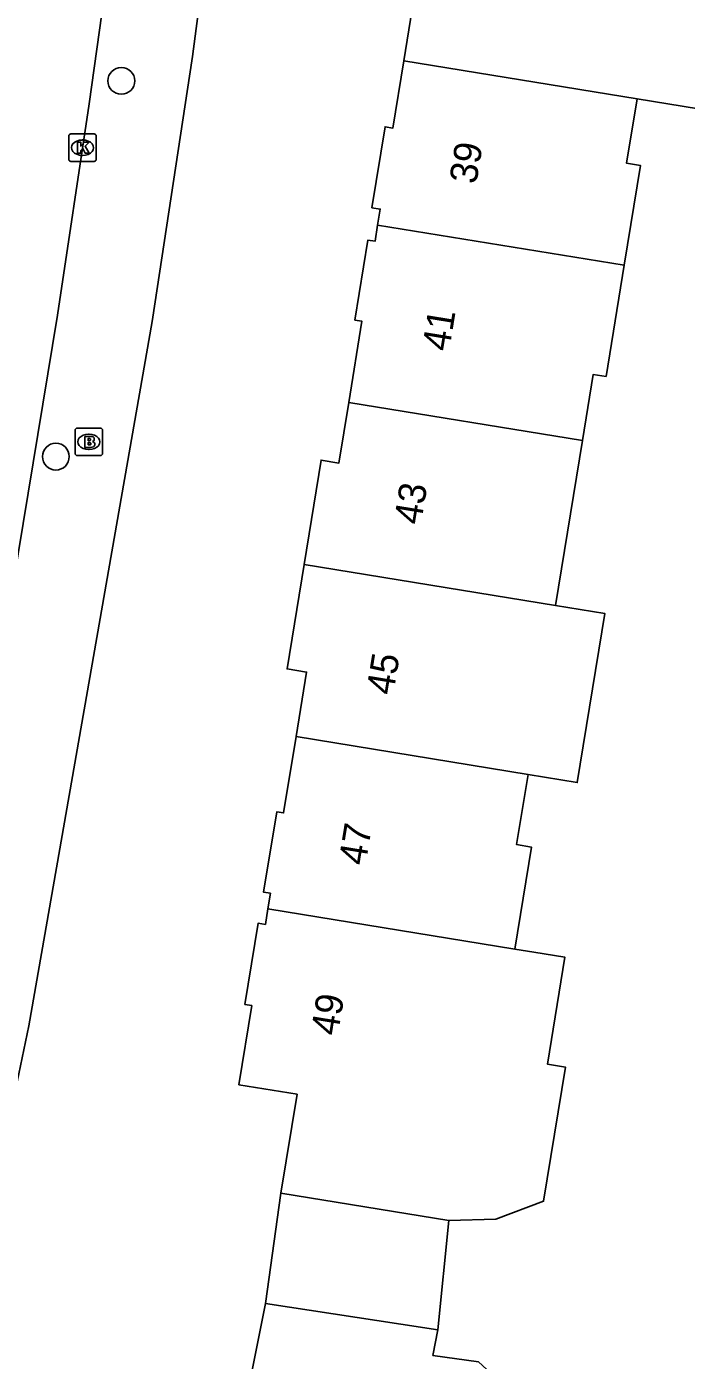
# Model space of a CAD drawing. Extents: x 161402 to 161933, y 381650 to 382313.
# Drawn here: x 161796.64 to 161820.7, y 381833.69 to 381882.31 of the extents above; entities that cross this region are included whole.
import ezdxf

# ---------------------------------------------------------------- set-up
doc = ezdxf.new("R2010")
doc.units = 0
for name, color, linetype in [('IMGEO_Boom', 7, 'Continuous'), ('IMGEO_Brandkraan', 7, 'Continuous'), ('IMGEO_Kolk', 7, 'Continuous'), ('IMGEO_Pand', 7, 'Continuous'), ('IMGEO_Pand_nummerreeks', 7, 'Continuous'), ('IMGEO_Pand_overbouw', 7, 'Continuous'), ('IMGEO_Rijbaan_lokaal_open', 7, 'Continuous'), ('IMGEO_Voetpad_open', 7, 'Continuous')]:
    doc.layers.add(name, color=color, linetype=linetype)

msp = doc.modelspace()

# ---------------------------------------------------------------- linework, layer by layer
at = {"layer": 'IMGEO_Boom'}
for centre in [(161800.09, 381880.338), (161797.701, 381866.639)]:
    msp.add_circle(centre, 0.489, dxfattribs=at)
at = {"layer": 'IMGEO_Brandkraan'}
for p, q in [((161798.404, 381866.751), (161798.404, 381867.603)), ((161798.479, 381867.677), (161799.331, 381867.677)), ((161799.405, 381867.603), (161799.405, 381866.751)), ((161798.892, 381867.457), (161798.917, 381867.457)), ((161799.331, 381866.677), (161798.479, 381866.677)), ((161798.915, 381866.897), (161798.89, 381866.897))]:
    msp.add_line(p, q, dxfattribs=at)
for points in [[(161798.404, 381866.751), (161798.404, 381867.603)], [(161798.479, 381867.677), (161799.331, 381867.677)], [(161799.405, 381867.603), (161799.405, 381866.751)], [(161798.752, 381867.377), (161798.752, 381866.977), (161798.965, 381866.977)], [(161798.983, 381867.377), (161798.752, 381867.377)], [(161798.931, 381867.296), (161798.877, 381867.296), (161798.877, 381867.22)], [(161798.877, 381867.22), (161798.93, 381867.22)], [(161798.939, 381867.144), (161798.877, 381867.144), (161798.877, 381867.063)], [(161798.877, 381867.063), (161798.939, 381867.063)], [(161799.331, 381866.677), (161798.479, 381866.677)]]:
    msp.add_lwpolyline(points, dxfattribs=at)
for centre, radius, start, end in [((161798.481, 381867.601), 0.0765, 91.552, 178.448), ((161798.481, 381867.601), 0.0765, 91.552, 178.448), ((161799.329, 381867.601), 0.0765, 1.552, 88.448), ((161799.329, 381867.601), 0.0765, 1.552, 88.448), ((161798.932, 381867.258), 0.0379, 267.8285, 90.9355), ((161798.94, 381867.103), 0.0404, 269.8759, 90.5077), ((161798.971, 381867.228), 0.251, 268.6676, 293.5347), ((161798.987, 381867.232), 0.145, 59.4692, 91.5367), ((161799.012, 381867.279), 0.0922, 285.5137, 58.1501), ((161799.017, 381867.087), 0.105, 301.3115, 78.989), ((161798.481, 381866.753), 0.0765, 181.552, 268.448), ((161798.481, 381866.753), 0.0765, 181.552, 268.448), ((161799.329, 381866.753), 0.0765, 271.552, 358.448), ((161799.329, 381866.753), 0.0765, 271.552, 358.448)]:
    msp.add_arc(centre, radius, start, end, dxfattribs=at)
for centre, major_axis, ratio, start_param, end_param in [((161798.891, 381867.177), (-0.387, 0.002), 0.722429, 4.712389, 7.853982), ((161798.916, 381867.177), (-0.39, 0.002), 0.717154, 1.570796, 4.712389)]:
    msp.add_ellipse(centre, major_axis=major_axis, ratio=ratio, start_param=start_param, end_param=end_param, dxfattribs=at)
at = {"layer": 'IMGEO_Kolk'}
for p, q in [((161798.173, 381877.476), (161798.173, 381878.328)), ((161798.248, 381878.402), (161799.1, 381878.402)), ((161798.661, 381878.182), (161798.686, 381878.182)), ((161799.174, 381878.328), (161799.174, 381877.476)), ((161799.1, 381877.402), (161798.248, 381877.402)), ((161798.684, 381877.622), (161798.659, 381877.622))]:
    msp.add_line(p, q, dxfattribs=at)
for points in [[(161798.173, 381877.476), (161798.173, 381878.328)], [(161798.248, 381878.402), (161799.1, 381878.402)], [(161799.174, 381878.328), (161799.174, 381877.476)], [(161798.494, 381878.102), (161798.617, 381878.102), (161798.617, 381877.951), (161798.747, 381878.102), (161798.911, 381878.102), (161798.765, 381877.951), (161798.918, 381877.702), (161798.766, 381877.702), (161798.681, 381877.866), (161798.617, 381877.799), (161798.617, 381877.702), (161798.494, 381877.702), (161798.494, 381878.102)], [(161799.1, 381877.402), (161798.248, 381877.402)]]:
    msp.add_lwpolyline(points, dxfattribs=at)
for centre, start, end in [((161798.25, 381878.326), 91.552, 178.448), ((161798.25, 381878.326), 91.552, 178.448), ((161799.098, 381878.326), 1.552, 88.448), ((161799.098, 381878.326), 1.552, 88.448), ((161798.25, 381877.478), 181.552, 268.448), ((161798.25, 381877.478), 181.552, 268.448), ((161799.098, 381877.478), 271.552, 358.448), ((161799.098, 381877.478), 271.552, 358.448)]:
    msp.add_arc(centre, 0.0765, start, end, dxfattribs=at)
for centre, major_axis, ratio, start_param, end_param in [((161798.66, 381877.902), (-0.387, 0.002), 0.722429, 4.712389, 7.853982), ((161798.685, 381877.902), (-0.39, 0.002), 0.717154, 1.570796, 4.712389)]:
    msp.add_ellipse(centre, major_axis=major_axis, ratio=ratio, start_param=start_param, end_param=end_param, dxfattribs=at)
at = {"layer": 'IMGEO_Pand'}
for points in [[(161810.395, 381881.067), (161810.826, 381883.715), (161810.164, 381883.823), (161810.785, 381887.636)], [(161819.956, 381886.143), (161823.31, 381885.597), (161822.259, 381879.139), (161818.905, 381879.685)], [(161809.44, 381875.075), (161809.536, 381875.662), (161809.228, 381875.712), (161809.709, 381878.662), (161809.996, 381878.615), (161810.395, 381881.067)], [(161810.395, 381881.067), (161818.905, 381879.685)], [(161818.905, 381879.685), (161818.522, 381877.335), (161819.026, 381877.253), (161818.433, 381873.614)], [(161808.383, 381868.61), (161808.866, 381871.576), (161808.608, 381871.617), (161809.083, 381874.532), (161809.345, 381874.489), (161809.44, 381875.075)], [(161818.433, 381873.614), (161809.44, 381875.075)], [(161818.433, 381873.614), (161817.773, 381869.56), (161817.303, 381869.637), (161816.91, 381867.225)], [(161806.758, 381862.706), (161807.378, 381866.511), (161808.024, 381866.406), (161808.383, 381868.61)], [(161816.91, 381867.225), (161808.383, 381868.61)], [(161816.91, 381867.225), (161815.931, 381861.211)], [(161806.462, 381856.43), (161806.845, 381858.783), (161806.138, 381858.899), (161806.758, 381862.706)], [(161815.931, 381861.211), (161806.758, 381862.706)], [(161815.931, 381861.211), (161817.728, 381860.918), (161816.724, 381854.757), (161814.927, 381855.05)], [(161805.439, 381850.152), (161805.531, 381850.718), (161805.279, 381850.759), (161805.756, 381853.688), (161806.009, 381853.647), (161806.462, 381856.43)], [(161806.462, 381856.43), (161814.927, 381855.05)], [(161814.927, 381855.05), (161814.511, 381852.494), (161815.051, 381852.406), (161814.445, 381848.684)], [(161814.445, 381848.684), (161815.143, 381848.57), (161816.274, 381848.386), (161815.639, 381844.486), (161816.292, 381844.38), (161815.496, 381839.494), (161813.752, 381838.834), (161812.038, 381838.787), (161805.913, 381839.785), (161806.5, 381843.39), (161804.376, 381843.736), (161804.846, 381846.625), (161804.595, 381846.666), (161805.077, 381849.626), (161805.346, 381849.583), (161805.439, 381850.152)], [(161805.439, 381850.152), (161814.445, 381848.684)], [(161807.293, 381824.968), (161807.841, 381824.851), (161814.646, 381832.225), (161813.116, 381833.637), (161811.453, 381833.871), (161811.638, 381834.801), (161810.288, 381835.006), (161805.344, 381835.758), (161804.632, 381832.178), (161799.282, 381833.241), (161798.723, 381830.429), (161798.505, 381830.355), (161797.96, 381827.609), (161798.189, 381827.564), (161798.062, 381826.928)]]:
    msp.add_lwpolyline(points, dxfattribs=at)
at = {"layer": 'IMGEO_Pand_overbouw'}
msp.add_lwpolyline([(161811.638, 381834.801), (161812.038, 381838.787), (161805.913, 381839.785), (161805.344, 381835.758), (161810.288, 381835.006)], close=True, dxfattribs=at)
at = {"layer": 'IMGEO_Rijbaan_lokaal_open'}
msp.add_lwpolyline([(161803.538, 381914.387), (161803.118, 381910.861), (161801.89, 381901.53), (161801.051, 381895.224), (161800.123, 381888.098), (161798.914, 381879.502), (161797.756, 381871.795), (161795.424, 381857.71)], dxfattribs=at)
at = {"layer": 'IMGEO_Voetpad_open'}
msp.add_lwpolyline([(161778.698, 381768.78), (161781.039, 381777.203), (161788.629, 381808.145), (161791.311, 381819.878), (161794.918, 381837.231), (161795.748, 381841.221), (161796.717, 381845.885), (161801.214, 381871.562), (161802.683, 381881.227), (161808.066, 381922.168), (161810.3, 381942.403)], dxfattribs=at)

# ---------------------------------------------------------------- texts
at = {"layer": 'IMGEO_Pand_nummerreeks'}
for s, rotation, p in [('39', 80.7599, (161813.036, 381876.545)), ('41', 80.7599, (161812.045, 381870.448)), ('43', 80.7599, (161811.016, 381864.126)), ('45', 80.7599, (161810.006, 381857.917)), ('47', 80.7599, (161808.996, 381851.707)), ('49', 80.7584, (161807.985, 381845.498))]:
    msp.add_text(s, height=1, rotation=rotation, dxfattribs=at).set_placement(p)

doc.saveas('drawing.dxf')
